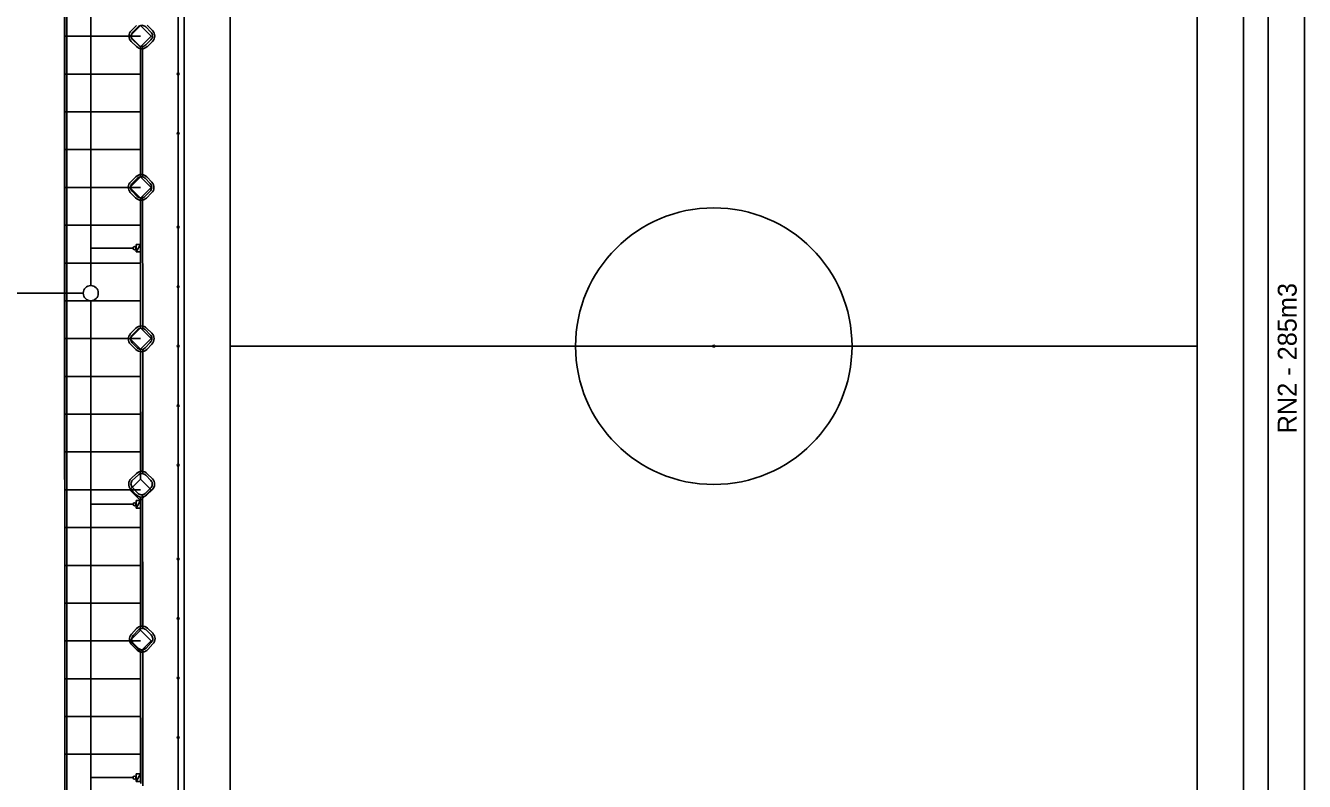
# Model space of a CAD drawing. Extents: x -264205 to -263659, y -1242401 to -1241986.
# Drawn here: x -264128.2 to -264043.5, y -1242269.8 to -1242219.8 of the extents above; entities that cross this region are included whole.
import ezdxf

# ---------------------------------------------------------------- set-up
doc = ezdxf.new("R2010")
doc.units = 0
for name, color, linetype in [('PROJEKT_OBRUBNIKY_KOMUNIKACIE', 7, 'Continuous'), ('PROJEKT_TDZ_VODOROVNE', 7, 'Continuous'), ('SITUACIA_DSP_2D', 7, 'Continuous'), ('SO_20-3_OBRUBNIKY_DOLNA_HRANA', 7, 'Continuous'), ('SO_20-3_OBRUBNIKY_HORNA_HRANA', 7, 'Continuous')]:
    doc.layers.add(name, color=color, linetype=linetype)

msp = doc.modelspace()

# ---------------------------------------------------------------- linework, layer by layer
at = {"layer": 'PROJEKT_OBRUBNIKY_KOMUNIKACIE'}
for p, q in [((-264125.568, -1242270.982), (-264125.568, -1242191.482)), ((-264120.568, -1242221.189), (-264120.568, -1242229.774)), ((-264120.568, -1242231.189), (-264120.568, -1242239.774)), ((-264120.568, -1242241.189), (-264120.568, -1242249.774)), ((-264120.568, -1242251.191), (-264120.568, -1242259.775)), ((-264120.568, -1242261.189), (-264120.568, -1242269.774))]:
    msp.add_line(p, q, dxfattribs=at)
for points in [[(-264117.668, -1242187.932), (-264047.568, -1242187.932), (-264047.568, -1242294.032), (-264117.668, -1242294.032), (-264117.668, -1242187.932)], [(-264120.568, -1242219.775), (-264119.861, -1242220.482), (-264120.568, -1242221.189), (-264121.275, -1242220.482), (-264120.568, -1242219.775)], [(-264120.568, -1242229.775), (-264119.861, -1242230.482), (-264120.568, -1242231.189), (-264121.275, -1242230.482), (-264120.568, -1242229.775)], [(-264120.568, -1242239.775), (-264119.861, -1242240.482), (-264120.568, -1242241.189), (-264121.275, -1242240.482), (-264120.568, -1242239.775)], [(-264120.568, -1242249.775), (-264119.861, -1242250.482), (-264120.568, -1242251.189), (-264121.275, -1242250.482), (-264120.568, -1242249.775)], [(-264120.568, -1242259.775), (-264119.861, -1242260.482), (-264120.568, -1242261.189), (-264121.275, -1242260.482), (-264120.568, -1242259.775)]]:
    msp.add_lwpolyline(points, dxfattribs=at)
at = {"layer": 'PROJEKT_TDZ_VODOROVNE'}
for p, q in [((-264125.568, -1242220.482), (-264120.568, -1242220.482)), ((-264125.568, -1242222.982), (-264120.568, -1242222.982)), ((-264125.568, -1242225.482), (-264120.568, -1242225.482)), ((-264125.568, -1242227.982), (-264120.568, -1242227.982)), ((-264125.568, -1242230.482), (-264120.568, -1242230.482)), ((-264125.568, -1242232.982), (-264120.568, -1242232.982)), ((-264125.568, -1242232.982), (-264120.568, -1242232.982)), ((-264125.568, -1242235.482), (-264120.568, -1242235.482)), ((-264125.568, -1242237.982), (-264120.568, -1242237.982)), ((-264125.568, -1242240.482), (-264120.568, -1242240.482)), ((-264125.568, -1242242.982), (-264120.568, -1242242.982)), ((-264125.568, -1242245.482), (-264120.568, -1242245.482)), ((-264125.568, -1242247.982), (-264120.568, -1242247.982)), ((-264125.568, -1242250.482), (-264120.568, -1242250.482)), ((-264125.568, -1242252.982), (-264120.568, -1242252.982)), ((-264125.568, -1242255.482), (-264120.568, -1242255.482)), ((-264125.568, -1242257.982), (-264120.568, -1242257.982)), ((-264125.568, -1242260.482), (-264120.568, -1242260.482)), ((-264125.568, -1242262.982), (-264120.568, -1242262.982)), ((-264125.568, -1242265.482), (-264120.568, -1242265.482)), ((-264125.568, -1242267.982), (-264120.568, -1242267.982))]:
    msp.add_line(p, q, dxfattribs=at)
at = {"layer": 'SITUACIA_DSP_2D'}
for p, q in [((-264118.068, -1242187.532), (-264118.068, -1242294.432)), ((-264117.668, -1242294.032), (-264117.668, -1242187.932)), ((-264047.568, -1242187.932), (-264047.568, -1242294.032)), ((-264114.618, -1242190.982), (-264114.618, -1242290.982)), ((-264050.618, -1242290.982), (-264050.618, -1242190.982)), ((-264045.927, -1242194.982), (-264045.927, -1242293.982)), ((-264043.527, -1242293.982), (-264043.527, -1242194.982)), ((-264123.854, -1242207), (-264123.854, -1242236.976)), ((-264121.275, -1242220.482), (-264120.568, -1242219.775)), ((-264120.568, -1242219.775), (-264119.861, -1242220.482)), ((-264120.568, -1242221.189), (-264121.275, -1242220.482)), ((-264119.861, -1242220.482), (-264120.568, -1242221.189)), ((-264120.568, -1242221.189), (-264120.568, -1242229.774)), ((-264118.008, -1242222.97), (-264118.128, -1242222.97)), ((-264118.068, -1242222.91), (-264118.068, -1242223.03)), ((-264118.008, -1242226.907), (-264118.128, -1242226.907)), ((-264118.068, -1242226.847), (-264118.068, -1242226.967)), ((-264121.275, -1242230.482), (-264120.568, -1242229.775)), ((-264120.568, -1242229.775), (-264119.861, -1242230.482)), ((-264120.568, -1242231.189), (-264121.275, -1242230.482)), ((-264119.861, -1242230.482), (-264120.568, -1242231.189)), ((-264120.568, -1242231.189), (-264120.568, -1242239.774)), ((-264118.008, -1242233.107), (-264118.128, -1242233.107)), ((-264118.068, -1242233.047), (-264118.068, -1242233.167)), ((-264121.058, -1242234.499), (-264123.854, -1242234.499)), ((-264120.858, -1242234.749), (-264120.858, -1242234.249)), ((-264120.858, -1242234.249), (-264120.568, -1242234.249)), ((-264120.858, -1242234.749), (-264120.568, -1242234.249)), ((-264120.858, -1242234.749), (-264120.568, -1242234.249)), ((-264120.568, -1242234.249), (-264120.858, -1242234.249)), ((-264120.858, -1242234.249), (-264120.858, -1242234.749)), ((-264120.568, -1242234.249), (-264120.568, -1242234.749)), ((-264120.568, -1242234.749), (-264120.858, -1242234.749)), ((-264118.008, -1242237.045), (-264118.128, -1242237.045)), ((-264118.068, -1242236.985), (-264118.068, -1242237.105)), ((-264154.318, -1242237.476), (-264124.354, -1242237.476)), ((-264123.854, -1242237.976), (-264123.854, -1242297.736)), ((-264121.275, -1242240.482), (-264120.568, -1242239.775)), ((-264120.568, -1242241.189), (-264121.275, -1242240.482)), ((-264120.568, -1242239.775), (-264119.861, -1242240.482)), ((-264119.861, -1242240.482), (-264120.568, -1242241.189)), ((-264120.568, -1242241.189), (-264120.568, -1242249.774)), ((-264118.008, -1242240.982), (-264118.128, -1242240.982)), ((-264118.068, -1242241.042), (-264118.068, -1242240.922)), ((-264050.618, -1242240.982), (-264114.618, -1242240.982)), ((-264118.008, -1242244.92), (-264118.128, -1242244.92)), ((-264118.068, -1242244.98), (-264118.068, -1242244.86)), ((-264118.008, -1242248.857), (-264118.128, -1242248.857)), ((-264118.068, -1242248.917), (-264118.068, -1242248.797)), ((-264121.275, -1242250.482), (-264120.568, -1242249.775)), ((-264120.568, -1242249.775), (-264119.861, -1242250.482)), ((-264120.568, -1242251.189), (-264121.275, -1242250.482)), ((-264119.861, -1242250.482), (-264120.568, -1242251.189)), ((-264121.057, -1242251.439), (-264123.853, -1242251.439)), ((-264120.857, -1242251.689), (-264120.857, -1242251.189)), ((-264120.857, -1242251.189), (-264120.567, -1242251.189)), ((-264120.857, -1242251.689), (-264120.567, -1242251.189)), ((-264120.857, -1242251.689), (-264120.567, -1242251.189)), ((-264120.567, -1242251.189), (-264120.857, -1242251.189)), ((-264120.857, -1242251.189), (-264120.857, -1242251.689)), ((-264120.568, -1242251.191), (-264120.568, -1242259.775)), ((-264120.567, -1242251.189), (-264120.567, -1242251.689)), ((-264120.567, -1242251.689), (-264120.857, -1242251.689)), ((-264118.008, -1242255.057), (-264118.128, -1242255.057)), ((-264118.068, -1242255.117), (-264118.068, -1242254.997)), ((-264118.008, -1242258.995), (-264118.128, -1242258.995)), ((-264118.068, -1242259.055), (-264118.068, -1242258.935)), ((-264121.275, -1242260.482), (-264120.568, -1242259.775)), ((-264120.568, -1242259.775), (-264119.861, -1242260.482)), ((-264120.568, -1242261.189), (-264121.275, -1242260.482)), ((-264119.861, -1242260.482), (-264120.568, -1242261.189)), ((-264120.568, -1242261.189), (-264120.568, -1242269.774)), ((-264118.008, -1242262.932), (-264118.128, -1242262.932)), ((-264118.068, -1242262.992), (-264118.068, -1242262.872)), ((-264118.008, -1242266.87), (-264118.128, -1242266.87)), ((-264118.068, -1242266.93), (-264118.068, -1242266.81)), ((-264121.058, -1242269.525), (-264123.854, -1242269.525)), ((-264120.857, -1242269.775), (-264120.857, -1242269.275)), ((-264120.857, -1242269.275), (-264120.567, -1242269.275)), ((-264120.857, -1242269.775), (-264120.567, -1242269.275)), ((-264120.857, -1242269.775), (-264120.567, -1242269.275)), ((-264120.567, -1242269.275), (-264120.857, -1242269.275)), ((-264120.857, -1242269.275), (-264120.857, -1242269.775)), ((-264120.567, -1242269.775), (-264120.857, -1242269.775)), ((-264120.567, -1242269.275), (-264120.567, -1242269.775))]:
    msp.add_line(p, q, dxfattribs=at)
for centre, radius in [((-264118.068, -1242222.97), 0.06), ((-264118.068, -1242226.907), 0.06), ((-264118.068, -1242233.107), 0.06), ((-264120.958, -1242234.499), 0.1), ((-264123.854, -1242237.476), 0.5), ((-264118.068, -1242237.045), 0.06), ((-264118.068, -1242240.982), 0.06), ((-264118.068, -1242244.92), 0.06), ((-264118.068, -1242248.857), 0.06), ((-264120.957, -1242251.439), 0.1), ((-264118.068, -1242255.057), 0.06), ((-264118.068, -1242258.995), 0.06), ((-264118.068, -1242262.932), 0.06), ((-264118.068, -1242266.87), 0.06), ((-264120.958, -1242269.525), 0.1)]:
    msp.add_circle(centre, radius, dxfattribs=at)
for radius, start, end in [(9.15, 360, 180), (9.15, 180, 360), (0.0605, 90, 270), (0.0605, 270, 90)]:
    msp.add_arc((-264082.618, -1242240.982), radius, start, end, dxfattribs=at)
at = {"layer": 'SO_20-3_OBRUBNIKY_DOLNA_HRANA'}
for p, q in [((-264120.826, -1242219.765), (-264121.176, -1242220.119)), ((-264120.126, -1242219.745), (-264119.763, -1242220.105)), ((-264120.826, -1242221.165), (-264121.172, -1242220.823)), ((-264119.769, -1242220.817), (-264120.124, -1242221.169)), ((-264120.565, -1242229.625), (-264120.571, -1242221.301)), ((-264121.209, -1242230.11), (-264120.864, -1242229.772)), ((-264120.15, -1242229.774), (-264119.802, -1242230.139)), ((-264120.883, -1242231.177), (-264121.234, -1242230.817)), ((-264119.823, -1242230.841), (-264120.169, -1242231.182)), ((-264120.554, -1242239.646), (-264120.56, -1242231.327)), ((-264121.213, -1242240.146), (-264120.864, -1242239.793)), ((-264120.16, -1242239.783), (-264119.81, -1242240.123)), ((-264120.863, -1242241.204), (-264121.219, -1242240.853)), ((-264119.809, -1242240.84), (-264120.148, -1242241.193)), ((-264120.55, -1242249.265), (-264120.554, -1242241.349)), ((-264121.182, -1242249.732), (-264120.824, -1242249.4)), ((-264120.115, -1242249.418), (-264119.77, -1242249.765)), ((-264120.864, -1242250.796), (-264121.194, -1242250.445)), ((-264119.796, -1242250.48), (-264120.161, -1242250.829)), ((-264120.548, -1242259.507), (-264120.56, -1242250.957)), ((-264121.162, -1242260.036), (-264120.821, -1242259.664)), ((-264120.107, -1242259.637), (-264119.754, -1242259.976)), ((-264120.776, -1242261.096), (-264121.139, -1242260.741)), ((-264119.736, -1242260.68), (-264120.077, -1242261.051)), ((-264120.537, -1242269.907), (-264120.555, -1242261.209))]:
    msp.add_line(p, q, dxfattribs=at)
for points in [[(-264125.573, -1242270.915), (-264125.578, -1242264.895), (-264125.575, -1242255.299), (-264125.581, -1242244.324), (-264125.582, -1242233.844), (-264125.584, -1242219.84), (-264125.593, -1242209.81), (-264125.59, -1242197.798), (-264125.59, -1242191.484)], [(-264125.429, -1242270.662), (-264125.437, -1242264.9), (-264125.431, -1242255.315), (-264125.435, -1242244.34), (-264125.439, -1242233.845), (-264125.44, -1242219.841), (-264125.448, -1242209.814), (-264125.447, -1242197.797), (-264125.435, -1242191.484)]]:
    msp.add_lwpolyline(points, dxfattribs=at)
for centre, major_axis, ratio, start_param, end_param in [((-264120.832, -1242220.469), (0.216, -0.441), 0.999979, 3.462744, 5.062042), ((-264120.123, -1242220.458), (0.183, 0.47), 0.998877, 4.292351, 5.859751), ((-264120.473, -1242220.812), (0.444, 0.228), 0.999924, 3.453691, 5.012696), ((-264120.863, -1242230.476), (0.378, -0.333), 0.999798, 3.050143, 4.60564), ((-264120.508, -1242230.12), (-0.447, -0.218), 0.99998, 3.456563, 5.056606), ((-264120.165, -1242230.48), (0.194, 0.458), 0.999375, 4.300208, 5.866467), ((-264120.524, -1242230.826), (0.502, -0.004), 0.999977, 3.921399, 5.503379), ((-264120.507, -1242240.147), (-0.499, -0.063), 0.999917, 3.825435, 5.37776), ((-264120.861, -1242240.502), (-0.137, -0.482), 0.999773, 4.197765, 5.764757), ((-264120.165, -1242240.482), (-0.208, 0.46), 0.999856, 3.500163, 5.07907), ((-264120.511, -1242240.856), (0.479, 0.128), 0.998676, 3.659329, 5.271157), ((-264120.853, -1242250.094), (-0.008, -0.489), 0.99979, 3.896384, 5.528394), ((-264120.478, -1242249.757), (-0.496, 0.013), 0.999976, 3.917165, 5.507613), ((-264120.125, -1242250.11), (-0.05, 0.493), 0.999948, 3.767556, 5.382488), ((-264120.496, -1242250.47), (0.231, 0.434), 0.99998, 2.785165, 4.380766), ((-264120.451, -1242259.991), (-0.446, 0.213), 0.999982, 4.387078, 6.003781), ((-264120.802, -1242260.377), (-0.169, -0.466), 0.999971, 4.300812, 5.883738), ((-264120.094, -1242260.337), (-0.243, 0.432), 0.999885, 3.436393, 5.015373), ((-264120.449, -1242260.728), (0.434, 0.234), 0.999977, 3.491254, 5.073033)]:
    msp.add_ellipse(centre, major_axis=major_axis, ratio=ratio, start_param=start_param, end_param=end_param, dxfattribs=at)
at = {"layer": 'SO_20-3_OBRUBNIKY_HORNA_HRANA'}
for p, q in [((-264121.064, -1242220.215), (-264120.722, -1242219.864)), ((-264120.216, -1242219.86), (-264119.869, -1242220.209)), ((-264120.726, -1242221.055), (-264121.069, -1242220.718)), ((-264119.875, -1242220.713), (-264120.213, -1242221.054)), ((-264120.42, -1242229.779), (-264120.429, -1242221.16)), ((-264121.109, -1242230.22), (-264120.76, -1242229.879)), ((-264120.252, -1242229.879), (-264119.921, -1242230.225)), ((-264120.776, -1242231.073), (-264121.119, -1242230.723)), ((-264120.414, -1242239.803), (-264120.418, -1242231.165)), ((-264119.93, -1242230.738), (-264120.272, -1242231.075)), ((-264121.11, -1242240.254), (-264120.762, -1242239.897)), ((-264120.263, -1242239.888), (-264119.92, -1242240.222)), ((-264120.754, -1242241.104), (-264121.112, -1242240.752)), ((-264120.405, -1242249.415), (-264120.41, -1242241.185)), ((-264119.916, -1242240.736), (-264120.254, -1242241.09)), ((-264121.082, -1242249.84), (-264120.725, -1242249.508)), ((-264120.214, -1242249.524), (-264119.873, -1242249.869)), ((-264120.755, -1242250.692), (-264121.086, -1242250.341)), ((-264119.899, -1242250.378), (-264120.258, -1242250.724)), ((-264120.405, -1242259.649), (-264120.42, -1242250.808)), ((-264121.047, -1242260.125), (-264120.713, -1242259.765)), ((-264120.216, -1242259.735), (-264119.858, -1242260.085)), ((-264120.685, -1242260.983), (-264121.038, -1242260.637)), ((-264119.847, -1242260.582), (-264120.184, -1242260.951)), ((-264120.399, -1242270.064), (-264120.411, -1242261.068))]:
    msp.add_line(p, q, dxfattribs=at)
for centre, major_axis, ratio, start_param, end_param in [((-264120.467, -1242220.104), (-0.348, -0.038), 0.999249, 3.8025, 5.417886), ((-264120.818, -1242220.469), (-0.004, -0.354), 0.998351, 3.922572, 5.502206), ((-264120.115, -1242220.458), (0.08, 0.341), 0.999323, 4.126273, 5.733445), ((-264120.47, -1242220.803), (0.356, 0.05), 0.998417, 3.778494, 5.368139), ((-264120.865, -1242230.477), (0.068, -0.348), 0.997854, 3.70915, 5.287368), ((-264120.506, -1242230.114), (-0.342, -0.05), 0.999153, 3.74362, 5.393103), ((-264120.171, -1242230.477), (0.16, 0.317), 0.998795, 4.356433, 5.972219), ((-264120.523, -1242230.834), (0.348, -0.001), 0.998886, 3.904066, 5.520712), ((-264120.863, -1242240.504), (-0.022, -0.351), 0.999429, 3.985395, 5.558342), ((-264120.508, -1242240.148), (-0.35, -0.068), 0.999401, 3.763697, 5.311979), ((-264120.15, -1242240.481), (0.058, 0.342), 0.999012, 4.052736, 5.724046), ((-264120.511, -1242240.844), (0.351, 0.059), 0.998294, 3.796516, 5.353487), ((-264120.477, -1242249.764), (-0.351, 0.062), 0.999629, 4.05561, 5.657259), ((-264120.842, -1242250.092), (-0.081, -0.339), 0.999363, 4.135616, 5.740237), ((-264120.132, -1242250.111), (0.001, 0.354), 0.999133, 3.862601, 5.467869), ((-264120.491, -1242250.471), (0.337, 0.069), 0.999736, 3.638527, 5.255914), ((-264120.45, -1242259.996), (-0.35, 0.016), 0.999265, 4.028104, 5.60664), ((-264120.788, -1242260.377), (-0.024, -0.36), 0.999723, 4.006897, 5.58404), ((-264120.099, -1242260.339), (-0.008, 0.35), 0.99958, 3.923297, 5.501481), ((-264120.45, -1242260.713), (0.344, 0.097), 0.99713, 3.722556, 5.278139)]:
    msp.add_ellipse(centre, major_axis=major_axis, ratio=ratio, start_param=start_param, end_param=end_param, dxfattribs=at)

# ---------------------------------------------------------------- texts
at = {"layer": 'SITUACIA_DSP_2D'}
msp.add_text('RN2 - 285m3', height=1.25, rotation=90, dxfattribs=at).set_placement((-264044.042, -1242246.747))

doc.saveas('drawing.dxf')
